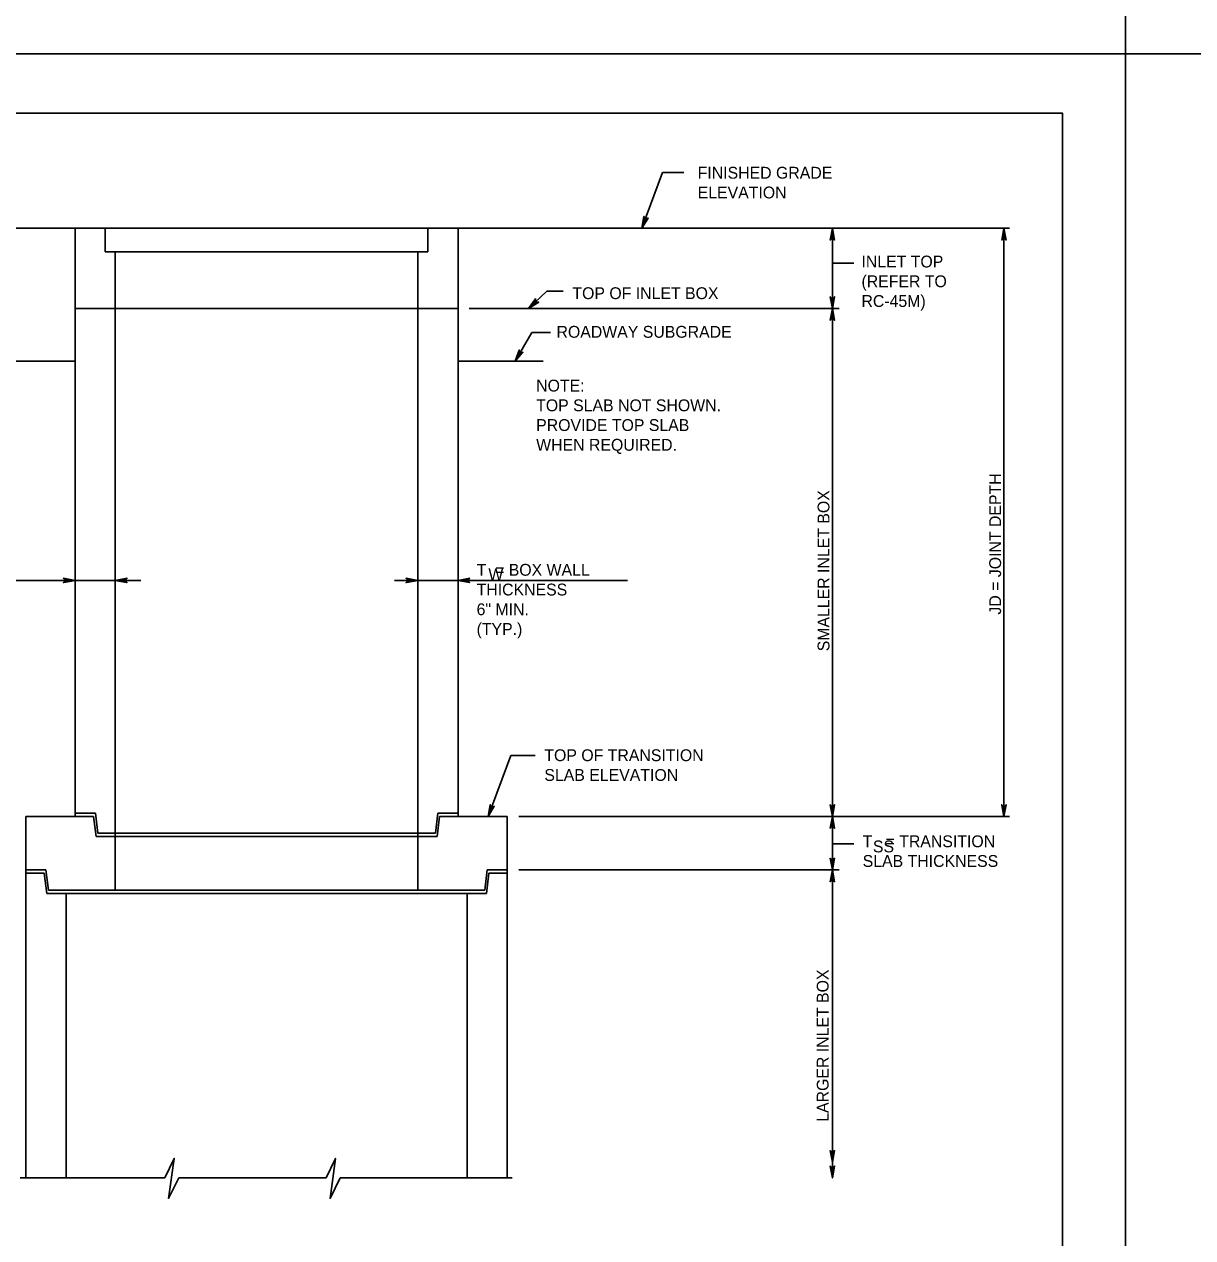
# Model space of a CAD drawing. Extents: x -6420 to 49575, y -4552 to 11624.
# Drawn here: x -4576 to -3605, y 2845 to 3853 of the extents above; entities that cross this region are included whole.
import ezdxf

# ---------------------------------------------------------------- set-up
doc = ezdxf.new("R2010")
doc.units = 0
doc.layers.add('1', color=7, linetype='Continuous')
doc.layers.add('PLT-BNDY', color=7, linetype='Continuous')

msp = doc.modelspace()

# ---------------------------------------------------------------- linework, layer by layer
at = {"layer": '1'}
for p, q in [((-4046, 3729.9), (-4063.1, 3683.7)), ((-4046, 3729.9), (-4028.1, 3729.9)), ((-4767.3, 3683.7), (-4533.9, 3683.7)), ((-4215.8, 3683.7), (-4533.9, 3683.7)), ((-4533.9, 3683.7), (-4533.9, 3194.8)), ((-4508.9, 3683.7), (-4508.9, 3664.2)), ((-4240.8, 3683.7), (-4240.8, 3664.2)), ((-4215.8, 3683.7), (-3757.7, 3683.7)), ((-4215.8, 3683.7), (-4215.8, 3194.8)), ((-3904.8, 3683.7), (-3904.8, 3617)), ((-3762.3, 3683.7), (-3762.3, 3194.8)), ((-4240.8, 3664.2), (-4508.9, 3664.2)), ((-4500.6, 3664.2), (-4500.6, 3617)), ((-4249.2, 3664.2), (-4249.2, 3617)), ((-3904.8, 3654.8), (-3887, 3654.8)), ((-4142.1, 3631.3), (-4157.2, 3617)), ((-4142.1, 3631.3), (-4128.4, 3631.3)), ((-4215.8, 3617), (-4533.9, 3617)), ((-4500.6, 3617), (-4500.6, 3133.7)), ((-4249.2, 3617), (-4249.2, 3133.7)), ((-4206.5, 3617), (-3899.2, 3617)), ((-3904.8, 3617), (-3904.8, 3150.4)), ((-4767.3, 3573.2), (-4533.9, 3573.2)), ((-4215.8, 3573.2), (-4145.2, 3573.2)), ((-4674.7, 3391), (-4479.3, 3391)), ((-4268.5, 3391), (-4074.9, 3391)), ((-4172, 3245.4), (-4190.8, 3194.8)), ((-4172, 3245.4), (-4151.8, 3245.4)), ((-4533.9, 3197.6), (-4517.2, 3197.6)), ((-4517.2, 3197.6), (-4515.2, 3180.9)), ((-4232.5, 3197.6), (-4234.6, 3180.9)), ((-4215.8, 3197.6), (-4232.5, 3197.6)), ((-4533.9, 3194.8), (-4574.9, 3194.8)), ((-4574.9, 2894.4), (-4574.9, 3194.8)), ((-4533.9, 3194.8), (-4518.6, 3194.8)), ((-4518.6, 3194.8), (-4516.5, 3178.1)), ((-4231.1, 3194.8), (-4233.2, 3178.1)), ((-4215.8, 3194.8), (-4231.1, 3194.8)), ((-4174.9, 3194.8), (-4215.8, 3194.8)), ((-4174.9, 2894.4), (-4174.9, 3194.8)), ((-4165.4, 3194.8), (-3757.7, 3194.8)), ((-4516.5, 3178.1), (-4500.6, 3178.1)), ((-4515.2, 3180.9), (-4500.6, 3180.9)), ((-4249.2, 3180.9), (-4500.6, 3180.9)), ((-4249.2, 3178.1), (-4500.6, 3178.1)), ((-4234.6, 3180.9), (-4249.2, 3180.9)), ((-4233.2, 3178.1), (-4249.2, 3178.1)), ((-3904.8, 3172.1), (-3887, 3172.1)), ((-4574.9, 3150.4), (-4558.2, 3150.4)), ((-4574.9, 3147.6), (-4559.6, 3147.6)), ((-4559.6, 3147.6), (-4557.5, 3130.9)), ((-4558.2, 3150.4), (-4556.1, 3133.7)), ((-4191.5, 3150.4), (-4193.6, 3133.7)), ((-4190.2, 3147.6), (-4192.2, 3130.9)), ((-4174.9, 3150.4), (-4191.5, 3150.4)), ((-4174.9, 3147.6), (-4190.2, 3147.6)), ((-4165.4, 3150.4), (-3899.2, 3150.4)), ((-3904.8, 3150.4), (-3904.8, 2894.4)), ((-4557.5, 3130.9), (-4541.5, 3130.9)), ((-4556.1, 3133.7), (-4541.5, 3133.7)), ((-4208.2, 3133.7), (-4541.5, 3133.7)), ((-4541.5, 2894.4), (-4541.5, 3130.9)), ((-4208.2, 3130.9), (-4541.5, 3130.9)), ((-4193.6, 3133.7), (-4208.2, 3133.7)), ((-4208.2, 2894.4), (-4208.2, 3130.9)), ((-4192.2, 3130.9), (-4208.2, 3130.9)), ((-4579.7, 2894.4), (-4459.5, 2894.4)), ((-4447.9, 2894.4), (-4325.5, 2894.4)), ((-4313.9, 2894.4), (-4170.8, 2894.4))]:
    msp.add_line(p, q, dxfattribs=at)
for points in [[(-3713.7, 1929), (-3713.7, 3779.4), (-6292.4, 3779.4), (-6292.4, 1929), (-3713.7, 1929), (-3713.7, 2015.5), (-4369.8, 2015.5), (-4369.8, 2227.7), (-3713.7, 2227.7), (-3713.7, 2322.7), (-4369.8, 2322.7), (-4369.8, 1929), (-4111.3, 1929), (-4111.3, 2015.5), (-4111.3, 1929), (-3858.7, 1929), (-3858.7, 2015.5), (-3858.7, 1975.1), (-3713.7, 1975.1)], [(-4063.1, 3683.7), (-4061.4, 3693.5), (-4061.3, 3693.1), (-4061.2, 3692.6), (-4060.9, 3692.3), (-4060.7, 3692), (-4060.4, 3691.9), (-4060.1, 3691.7), (-4059.8, 3691.6), (-4059.4, 3691.6), (-4059.1, 3691.6), (-4058.7, 3691.7), (-4058.3, 3692), (-4057.9, 3692.2), (-4063.1, 3683.7), (-4058.3, 3692), (-4058.7, 3691.7), (-4063.1, 3683.7), (-4059.1, 3691.6), (-4059.4, 3691.6), (-4063.1, 3683.7), (-4059.8, 3691.6), (-4060.1, 3691.7), (-4063.1, 3683.7), (-4060.4, 3691.9), (-4060.7, 3692), (-4063.1, 3683.7), (-4060.9, 3692.3), (-4061.2, 3692.6), (-4063.1, 3683.7), (-4061.3, 3693.1)], [(-3904.8, 3683.7), (-3903, 3673.9), (-3903.2, 3674.3), (-3903.5, 3674.7), (-3903.8, 3674.9), (-3904.2, 3675), (-3904.5, 3675.1), (-3904.8, 3675.2), (-3905.1, 3675.1), (-3905.5, 3675), (-3905.8, 3674.9), (-3906.1, 3674.7), (-3906.4, 3674.3), (-3906.6, 3673.9), (-3904.8, 3683.7), (-3906.4, 3674.3), (-3906.1, 3674.7), (-3904.8, 3683.7), (-3905.8, 3674.9), (-3905.5, 3675), (-3904.8, 3683.7), (-3905.1, 3675.1), (-3904.8, 3675.2), (-3904.8, 3683.7), (-3904.5, 3675.1), (-3904.2, 3675), (-3904.8, 3683.7), (-3903.8, 3674.9), (-3903.5, 3674.7), (-3904.8, 3683.7), (-3903.2, 3674.3)], [(-3762.3, 3683.7), (-3760.4, 3673.9), (-3760.7, 3674.3), (-3761, 3674.7), (-3761.3, 3674.9), (-3761.6, 3675), (-3761.9, 3675.1), (-3762.3, 3675.2), (-3762.6, 3675.1), (-3762.9, 3675), (-3763.3, 3674.9), (-3763.6, 3674.7), (-3763.8, 3674.3), (-3764.1, 3673.9), (-3762.3, 3683.7), (-3763.8, 3674.3), (-3763.6, 3674.7), (-3762.3, 3683.7), (-3763.3, 3674.9), (-3762.9, 3675), (-3762.3, 3683.7), (-3762.6, 3675.1), (-3762.3, 3675.2), (-3762.3, 3683.7), (-3761.9, 3675.1), (-3761.6, 3675), (-3762.3, 3683.7), (-3761.3, 3674.9), (-3761, 3674.7), (-3762.3, 3683.7), (-3760.7, 3674.3)], [(-4157.2, 3617), (-4151.4, 3625.1), (-4151.5, 3624.6), (-4151.6, 3624.2), (-4151.5, 3623.8), (-4151.4, 3623.4), (-4151.2, 3623.1), (-4151, 3622.9), (-4150.8, 3622.7), (-4150.5, 3622.5), (-4150.1, 3622.4), (-4149.8, 3622.3), (-4149.3, 3622.3), (-4148.8, 3622.4), (-4157.2, 3617), (-4149.3, 3622.3), (-4149.8, 3622.3), (-4157.2, 3617), (-4150.1, 3622.4), (-4150.5, 3622.5), (-4157.2, 3617), (-4150.8, 3622.7), (-4151, 3622.9), (-4157.2, 3617), (-4151.2, 3623.1), (-4151.4, 3623.4), (-4157.2, 3617), (-4151.5, 3623.8), (-4151.6, 3624.2), (-4157.2, 3617), (-4151.5, 3624.6)], [(-3904.8, 3617), (-3903, 3626.8), (-3903.2, 3626.4), (-3903.5, 3626.1), (-3903.8, 3625.9), (-3904.2, 3625.7), (-3904.5, 3625.6), (-3904.8, 3625.6), (-3905.1, 3625.6), (-3905.5, 3625.7), (-3905.8, 3625.9), (-3906.1, 3626.1), (-3906.4, 3626.4), (-3906.6, 3626.8), (-3904.8, 3617), (-3906.4, 3626.4), (-3906.1, 3626.1), (-3904.8, 3617), (-3905.8, 3625.9), (-3905.5, 3625.7), (-3904.8, 3617), (-3905.1, 3625.6), (-3904.8, 3625.6), (-3904.8, 3617), (-3904.5, 3625.6), (-3904.2, 3625.7), (-3904.8, 3617), (-3903.8, 3625.9), (-3903.5, 3626.1), (-3904.8, 3617), (-3903.2, 3626.4)], [(-3904.8, 3617), (-3903, 3607.2), (-3903.2, 3607.6), (-3903.5, 3608), (-3903.8, 3608.2), (-3904.2, 3608.4), (-3904.5, 3608.4), (-3904.8, 3608.5), (-3905.1, 3608.4), (-3905.5, 3608.4), (-3905.8, 3608.2), (-3906.1, 3608), (-3906.4, 3607.6), (-3906.6, 3607.2), (-3904.8, 3617), (-3906.4, 3607.6), (-3906.1, 3608), (-3904.8, 3617), (-3905.8, 3608.2), (-3905.5, 3608.4), (-3904.8, 3617), (-3905.1, 3608.4), (-3904.8, 3608.5), (-3904.8, 3617), (-3904.5, 3608.4), (-3904.2, 3608.4), (-3904.8, 3617), (-3903.8, 3608.2), (-3903.5, 3608), (-3904.8, 3617), (-3903.2, 3607.6)], [(-4168.3, 3573.2), (-4154.5, 3597), (-4139.1, 3597)], [(-4168.3, 3573.2), (-4165, 3582.5), (-4165, 3582.1), (-4164.9, 3581.6), (-4164.7, 3581.3), (-4164.6, 3581), (-4164.3, 3580.8), (-4164, 3580.5), (-4163.7, 3580.4), (-4163.4, 3580.3), (-4163, 3580.3), (-4162.7, 3580.3), (-4162.3, 3580.5), (-4161.8, 3580.7), (-4168.3, 3573.2), (-4162.3, 3580.5), (-4162.7, 3580.3), (-4168.3, 3573.2), (-4163, 3580.3), (-4163.4, 3580.3), (-4168.3, 3573.2), (-4163.7, 3580.4), (-4164, 3580.5), (-4168.3, 3573.2), (-4164.3, 3580.8), (-4164.6, 3581), (-4168.3, 3573.2), (-4164.7, 3581.3), (-4164.9, 3581.6), (-4168.3, 3573.2), (-4165, 3582.1)], [(-4533.9, 3391), (-4543.7, 3389.2), (-4543.3, 3389.4), (-4542.9, 3389.7), (-4542.7, 3390), (-4542.5, 3390.3), (-4542.5, 3390.7), (-4542.4, 3391), (-4542.5, 3391.3), (-4542.5, 3391.7), (-4542.7, 3392), (-4542.9, 3392.3), (-4543.3, 3392.6), (-4543.7, 3392.8), (-4533.9, 3391), (-4543.3, 3392.6), (-4542.9, 3392.3), (-4533.9, 3391), (-4542.7, 3392), (-4542.5, 3391.7), (-4533.9, 3391), (-4542.5, 3391.3), (-4542.4, 3391), (-4533.9, 3391), (-4542.5, 3390.7), (-4542.5, 3390.3), (-4533.9, 3391), (-4542.7, 3390), (-4542.9, 3389.7), (-4533.9, 3391), (-4543.3, 3389.4)], [(-4500.6, 3391), (-4490.8, 3392.8), (-4491.2, 3392.6), (-4491.5, 3392.3), (-4491.7, 3392), (-4491.9, 3391.7), (-4492, 3391.3), (-4492, 3391), (-4492, 3390.7), (-4491.9, 3390.3), (-4491.7, 3390), (-4491.5, 3389.7), (-4491.2, 3389.4), (-4490.8, 3389.2), (-4500.6, 3391), (-4491.2, 3389.4), (-4491.5, 3389.7), (-4500.6, 3391), (-4491.7, 3390), (-4491.9, 3390.3), (-4500.6, 3391), (-4492, 3390.7), (-4492, 3391), (-4500.6, 3391), (-4492, 3391.3), (-4491.9, 3391.7), (-4500.6, 3391), (-4491.7, 3392), (-4491.5, 3392.3), (-4500.6, 3391), (-4491.2, 3392.6)], [(-4249.2, 3391), (-4259, 3389.2), (-4258.6, 3389.4), (-4258.2, 3389.7), (-4258, 3390), (-4257.8, 3390.3), (-4257.8, 3390.7), (-4257.7, 3391), (-4257.8, 3391.3), (-4257.8, 3391.7), (-4258, 3392), (-4258.2, 3392.3), (-4258.6, 3392.6), (-4259, 3392.8), (-4249.2, 3391), (-4258.6, 3392.6), (-4258.2, 3392.3), (-4249.2, 3391), (-4258, 3392), (-4257.8, 3391.7), (-4249.2, 3391), (-4257.8, 3391.3), (-4257.7, 3391), (-4249.2, 3391), (-4257.8, 3390.7), (-4257.8, 3390.3), (-4249.2, 3391), (-4258, 3390), (-4258.2, 3389.7), (-4249.2, 3391), (-4258.6, 3389.4)], [(-4215.8, 3391), (-4206.1, 3392.8), (-4206.4, 3392.6), (-4206.8, 3392.3), (-4207, 3392), (-4207.2, 3391.7), (-4207.3, 3391.3), (-4207.3, 3391), (-4207.3, 3390.7), (-4207.2, 3390.3), (-4207, 3390), (-4206.8, 3389.7), (-4206.4, 3389.4), (-4206.1, 3389.2), (-4215.8, 3391), (-4206.4, 3389.4), (-4206.8, 3389.7), (-4215.8, 3391), (-4207, 3390), (-4207.2, 3390.3), (-4215.8, 3391), (-4207.3, 3390.7), (-4207.3, 3391), (-4215.8, 3391), (-4207.3, 3391.3), (-4207.2, 3391.7), (-4215.8, 3391), (-4207, 3392), (-4206.8, 3392.3), (-4215.8, 3391), (-4206.4, 3392.6)], [(-4190.8, 3194.8), (-4189.1, 3204.6), (-4189, 3204.2), (-4188.9, 3203.7), (-4188.6, 3203.4), (-4188.4, 3203.1), (-4188.1, 3203), (-4187.8, 3202.8), (-4187.5, 3202.7), (-4187.2, 3202.7), (-4186.8, 3202.7), (-4186.4, 3202.8), (-4186, 3203.1), (-4185.7, 3203.3), (-4190.8, 3194.8), (-4186, 3203.1), (-4186.4, 3202.8), (-4190.8, 3194.8), (-4186.8, 3202.7), (-4187.2, 3202.7), (-4190.8, 3194.8), (-4187.5, 3202.7), (-4187.8, 3202.8), (-4190.8, 3194.8), (-4188.1, 3203), (-4188.4, 3203.1), (-4190.8, 3194.8), (-4188.6, 3203.4), (-4188.9, 3203.7), (-4190.8, 3194.8), (-4189, 3204.2)], [(-3904.8, 3194.8), (-3903, 3204.6), (-3903.2, 3204.2), (-3903.5, 3203.8), (-3903.8, 3203.6), (-3904.2, 3203.4), (-3904.5, 3203.4), (-3904.8, 3203.3), (-3905.1, 3203.4), (-3905.5, 3203.4), (-3905.8, 3203.6), (-3906.1, 3203.8), (-3906.4, 3204.2), (-3906.6, 3204.6), (-3904.8, 3194.8), (-3906.4, 3204.2), (-3906.1, 3203.8), (-3904.8, 3194.8), (-3905.8, 3203.6), (-3905.5, 3203.4), (-3904.8, 3194.8), (-3905.1, 3203.4), (-3904.8, 3203.3), (-3904.8, 3194.8), (-3904.5, 3203.4), (-3904.2, 3203.4), (-3904.8, 3194.8), (-3903.8, 3203.6), (-3903.5, 3203.8), (-3904.8, 3194.8), (-3903.2, 3204.2)], [(-3762.3, 3194.8), (-3764.1, 3204.6), (-3763.8, 3204.2), (-3763.6, 3203.8), (-3763.3, 3203.6), (-3762.9, 3203.4), (-3762.6, 3203.4), (-3762.3, 3203.3), (-3761.9, 3203.4), (-3761.6, 3203.4), (-3761.3, 3203.6), (-3761, 3203.8), (-3760.7, 3204.2), (-3760.4, 3204.6), (-3762.3, 3194.8), (-3760.7, 3204.2), (-3761, 3203.8), (-3762.3, 3194.8), (-3761.3, 3203.6), (-3761.6, 3203.4), (-3762.3, 3194.8), (-3761.9, 3203.4), (-3762.3, 3203.3), (-3762.3, 3194.8), (-3762.6, 3203.4), (-3762.9, 3203.4), (-3762.3, 3194.8), (-3763.3, 3203.6), (-3763.6, 3203.8), (-3762.3, 3194.8), (-3763.8, 3204.2)], [(-3904.8, 3194.8), (-3903, 3185), (-3903.2, 3185.4), (-3903.5, 3185.8), (-3903.8, 3186), (-3904.2, 3186.2), (-3904.5, 3186.2), (-3904.8, 3186.3), (-3905.1, 3186.2), (-3905.5, 3186.2), (-3905.8, 3186), (-3906.1, 3185.8), (-3906.4, 3185.4), (-3906.6, 3185), (-3904.8, 3194.8), (-3906.4, 3185.4), (-3906.1, 3185.8), (-3904.8, 3194.8), (-3905.8, 3186), (-3905.5, 3186.2), (-3904.8, 3194.8), (-3905.1, 3186.2), (-3904.8, 3186.3), (-3904.8, 3194.8), (-3904.5, 3186.2), (-3904.2, 3186.2), (-3904.8, 3194.8), (-3903.8, 3186), (-3903.5, 3185.8), (-3904.8, 3194.8), (-3903.2, 3185.4)], [(-3904.8, 3150.4), (-3903, 3160.1), (-3903.2, 3159.8), (-3903.5, 3159.4), (-3903.8, 3159.2), (-3904.2, 3159), (-3904.5, 3158.9), (-3904.8, 3158.9), (-3905.1, 3158.9), (-3905.5, 3159), (-3905.8, 3159.2), (-3906.1, 3159.4), (-3906.4, 3159.8), (-3906.6, 3160.1), (-3904.8, 3150.4), (-3906.4, 3159.8), (-3906.1, 3159.4), (-3904.8, 3150.4), (-3905.8, 3159.2), (-3905.5, 3159), (-3904.8, 3150.4), (-3905.1, 3158.9), (-3904.8, 3158.9), (-3904.8, 3150.4), (-3904.5, 3158.9), (-3904.2, 3159), (-3904.8, 3150.4), (-3903.8, 3159.2), (-3903.5, 3159.4), (-3904.8, 3150.4), (-3903.2, 3159.8)], [(-3904.8, 3150.4), (-3903, 3140.6), (-3903.2, 3140.9), (-3903.5, 3141.3), (-3903.8, 3141.5), (-3904.2, 3141.7), (-3904.5, 3141.8), (-3904.8, 3141.8), (-3905.1, 3141.8), (-3905.5, 3141.7), (-3905.8, 3141.5), (-3906.1, 3141.3), (-3906.4, 3140.9), (-3906.6, 3140.6), (-3904.8, 3150.4), (-3906.4, 3140.9), (-3906.1, 3141.3), (-3904.8, 3150.4), (-3905.8, 3141.5), (-3905.5, 3141.7), (-3904.8, 3150.4), (-3905.1, 3141.8), (-3904.8, 3141.8), (-3904.8, 3150.4), (-3904.5, 3141.8), (-3904.2, 3141.7), (-3904.8, 3150.4), (-3903.8, 3141.5), (-3903.5, 3141.3), (-3904.8, 3150.4), (-3903.2, 3140.9)], [(-3904.8, 2907.5), (-3903, 2917.2), (-3903.2, 2916.9), (-3903.5, 2916.5), (-3903.8, 2916.3), (-3904.2, 2916.1), (-3904.5, 2916), (-3904.8, 2916), (-3905.1, 2916), (-3905.5, 2916.1), (-3905.8, 2916.3), (-3906.1, 2916.5), (-3906.4, 2916.9), (-3906.6, 2917.2), (-3904.8, 2907.5), (-3906.4, 2916.9), (-3906.1, 2916.5), (-3904.8, 2907.5), (-3905.8, 2916.3), (-3905.5, 2916.1), (-3904.8, 2907.5), (-3905.1, 2916), (-3904.8, 2916), (-3904.8, 2907.5), (-3904.5, 2916), (-3904.2, 2916.1), (-3904.8, 2907.5), (-3903.8, 2916.3), (-3903.5, 2916.5), (-3904.8, 2907.5), (-3903.2, 2916.9)], [(-4447.9, 2894.4), (-4456.3, 2877.4), (-4451.7, 2910.7), (-4459.5, 2894.4)], [(-4313.9, 2894.4), (-4322.2, 2877.4), (-4317.7, 2910.7), (-4325.5, 2894.4)], [(-3904.8, 2894.4), (-3903, 2904.2), (-3903.2, 2903.8), (-3903.5, 2903.4), (-3903.8, 2903.2), (-3904.2, 2903), (-3904.5, 2903), (-3904.8, 2902.9), (-3905.1, 2903), (-3905.5, 2903), (-3905.8, 2903.2), (-3906.1, 2903.4), (-3906.4, 2903.8), (-3906.6, 2904.2), (-3904.8, 2894.4), (-3906.4, 2903.8), (-3906.1, 2903.4), (-3904.8, 2894.4), (-3905.8, 2903.2), (-3905.5, 2903), (-3904.8, 2894.4), (-3905.1, 2903), (-3904.8, 2902.9), (-3904.8, 2894.4), (-3904.5, 2903), (-3904.2, 2903), (-3904.8, 2894.4), (-3903.8, 2903.2), (-3903.5, 2903.4), (-3904.8, 2894.4), (-3903.2, 2903.8)]]:
    msp.add_lwpolyline(points, dxfattribs=at)
at = {"layer": 'PLT-BNDY'}
for points in [[(-6420.4, 5777.4), (-3661.2, 5777.4), (-3661.2, 3828.6), (-6420.4, 3828.6)], [(-3661.2, 5777.4), (-902, 5777.4), (-902, 3828.6), (-3661.2, 3828.6)], [(-6420.4, 3828.6), (-3661.2, 3828.6), (-3661.2, 1879.8), (-6420.4, 1879.8)], [(-3661.2, 3828.6), (-902, 3828.6), (-902, 1879.8), (-3661.2, 1879.8)]]:
    msp.add_lwpolyline(points, close=True, dxfattribs=at)

# ---------------------------------------------------------------- texts
at = {"layer": '1'}
for s, height, p in [('FINISHED GRADE', 9.843, (-4016.7, 3724.9)), ('ELEVATION', 9.84, (-4016.7, 3708.5)), ('INLET TOP', 9.84, (-3880.6, 3651.1)), ('(REFER TO', 9.84, (-3880.6, 3634.7)), ('TOP OF INLET BOX', 9.843, (-4120.8, 3624.8)), ('RC-45M)', 9.84, (-3880.6, 3618.3)), ('ROADWAY SUBGRADE', 9.843, (-4134, 3592.7)), ('NOTE:', 9.84, (-4150.9, 3548)), ('TOP SLAB NOT SHOWN.', 9.843, (-4150.9, 3531.6)), ('PROVIDE TOP SLAB', 9.843, (-4150.9, 3515.2)), ('WHEN REQUIRED.', 9.843, (-4150.9, 3498.8)), ('T  = BOX WALL', 9.843, (-4200.4, 3394.9)), ('W', 9.84, (-4190.6, 3391.1)), ('THICKNESS', 9.84, (-4200.4, 3378.5)), ('6" MIN.', 9.84, (-4200.4, 3362.1)), ('(TYP.)', 9.84, (-4200.4, 3345.7)), ('TOP OF TRANSITION', 9.843, (-4144.1, 3240.8)), ('SLAB ELEVATION', 9.843, (-4144.1, 3224.4)), ('T   = TRANSITION', 9.843, (-3879.6, 3169.3)), ('SS', 9.84, (-3871.1, 3165)), ('SLAB THICKNESS', 9.843, (-3879.6, 3152.9))]:
    msp.add_text(s, height=height, dxfattribs=at).set_placement(p)
for s, p in [('JD = JOINT DEPTH', (-3764.6, 3362.6)), ('SMALLER INLET BOX', (-3907.2, 3332.1)), ('LARGER INLET BOX', (-3907.9, 2941.1))]:
    msp.add_text(s, height=9.843, rotation=90, dxfattribs=at).set_placement(p)

doc.saveas('drawing.dxf')
